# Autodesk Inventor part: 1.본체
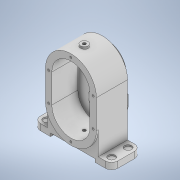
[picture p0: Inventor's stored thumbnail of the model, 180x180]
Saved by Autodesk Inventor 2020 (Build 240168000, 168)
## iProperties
Created: 2021-05
Part Number: 1.본체
Material: 일반
Document SubType Name: Modeling
Designer: Owner
Density: 1 g/cm^3
Appearance: 기본값
Author: Owner
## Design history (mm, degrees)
sketch "스케치1"
  geometry: L1 (0, 62.5)-(0, -62.5); L2 (40, 22.5)-(40, -22.5); L3 (-40, -22.5)-(-40, 22.5); A1 r 40 centre (0, 22.5) between (40, 22.5) and (-40, 22.5); A2 r 40 centre (0, -22.5) between (-40, -22.5) and (40, -22.5); 2 further points
  constraints: 8 end point, 6 point on circle, 4 tangent, 2 centre point, 2 point on line, 1 coincident, 1 midpoint, 1 parallel, 1 vertical
  dimensions: "d4" = 80 distance between parallel lines of L2 L3; "d5" = 45 distance of A2.centre A1.centre
extrude "돌출1" new body sketch "스케치1" distance "d6" = 49; taper "d7" = 0 deg
sketch "스케치2"
  geometry: L1 (0, 52.5)-(0, -52.5); L2 (-30, 22.5)-(-30, -22.5); L3 (30, -22.5)-(30, 22.5); A1 r 30 centre (0, 22.5) between (30, 22.5) and (-30, 22.5); A2 r 30 centre (0, -22.5) between (-30, -22.5) and (30, -22.5); 2 further points
  constraints: 8 end point, 6 point on circle, 4 tangent, 2 centre point, 2 point on line, 1 coincident, 1 midpoint, 1 parallel, 1 vertical
  dimensions: "d9" = 30 radius of A1; "d10" = 45 distance of A2.centre A1.centre
extrude "돌출2" cut sketch "스케치2" distance "d11" = 41; taper "d12" = 0 deg
sketch "스케치3"
  geometry: A1 r 40 centre (0, -22.5) between (-40, -22.5) and (40, -22.5) reference; A2 r 40 centre (0, 22.5) between (40, 22.5) and (-40, 22.5) reference; 1 further point
sketch "스케치4"
  geometry: L1 (-40, -22.5)-(-40, -59.5); L2 (-40, -59.5)-(-61, -59.5); L3 (-61, -59.5)-(-61, -69.5); L4 (-61, -69.5)-(-35, -69.5); L5 (-35, -69.5)-(-35, -64.5); L6 (-35, -64.5)-(0, -64.5); L7 (0, -64.5)-(0, -62.5); A1 r 40 centre (0, -22.5) between (-40, -22.5) and (40, -22.5) reference; 1 further point
  constraints: 14 end point, 6 perpendicular, 1 point on circle, 1 point on line, 1 tangent, 1 vertical
  dimensions: "d20" = 35 distance between parallel lines of L7 L5; "d21" = 10 distance of L2.end L3.end; "d22" = 5 distance between parallel lines of L6 L4; "d23" = 61 distance between parallel lines of L7 L3; "d24" = 47 distance from line of A1.centre L4
extrude "돌출3" join sketch "스케치4" distance "d25" = 46; taper "d26" = 0 deg
sketch "스케치5"
  geometry: L1 (0, 57.5)-(0, -57.5); L2 (-35, 22.5)-(-35, -22.5); L3 (35, -22.5)-(35, 22.5); A1 r 35 centre (0, 22.5) between (35, 22.5) and (-35, 22.5); A2 r 35 centre (0, -22.5) between (-35, -22.5) and (35, -22.5); 6 further points
  constraints: 8 end point, 6 point on circle, 5 coincident, 4 tangent, 2 centre point, 2 point on line, 1 midpoint, 1 parallel, 1 vertical
  dimensions: "d28" = 45 distance of A2.centre A1.centre
hole "구멍1" sketch "스케치5" diameter "d29" = 3.242; stored, may be unused: countersink angle "d33" = 82 deg, drill point angle "d35" = 118 deg; dims "d30" = 8, "d31" = 3.023, "d32" = 2, "d34" = 10
hole "구멍2" sketch "스케치5" diameter "d36" = 3.242; stored, may be unused: countersink angle "d40" = 82 deg, drill point angle "d42" = 118 deg; dims "d37" = 8, "d38" = 3.023, "d39" = 2, "d41" = 10
sketch "스케치6"
  geometry: 1 further point
node "작업 평면1"
sketch "스케치7"
  geometry: L1 (5, 49)-(-75, 49) reference; C1 r 6 at (-35, 28); 1 further point
  constraints: 1 centre point
  dimensions: "d44" = 21 distance from line of L1 C1.centre; "d45" = 12 diameter of C1
extrude "돌출4" join sketch "스케치7" stored distance "d46" = 46; taper "d47" = 0 deg
sketch "스케치8"
  geometry: L1 (-64.5, 0)-(-64.5, 46) reference; L2 (-52.5, 49)-(-22.5, 49) reference; 2 further points
  constraints: 1 point on line
  dimensions: "d48" = 21 distance from line of point (-64.5, 28) L2
sketch "스케치9"
  geometry: C1 r 6 at (-35, 28) reference; 2 further points
  constraints: 1 coincident
hole "구멍3" sketch "스케치9" at (-35, 28) diameter "d49" = 4.917; stored, may be unused: countersink angle "d53" = 82 deg, drill point angle "d55" = 118 deg; dims "d50" = 135, "d51" = 12, "d52" = 1, "d54" = 151.35
sketch "스케치10"
  geometry: L1 (0, 52.5)-(0, -52.5); L2 (-30, 22.5)-(-30, -22.5); L3 (30, -22.5)-(30, 22.5); A1 r 30 centre (0, 22.5) between (30, 22.5) and (-30, 22.5); A2 r 30 centre (0, -22.5) between (-30, -22.5) and (30, -22.5); 2 further points
  constraints: 8 end point, 6 point on circle, 4 tangent, 2 centre point, 2 point on line, 1 coincident, 1 midpoint, 1 parallel, 1 vertical
  dimensions: "d56" = 30 radius of A1; "d57" = 45 distance of A2.centre A1.centre
extrude "돌출5" join sketch "스케치10" distance "d58" = 11; taper "d59" = 0 deg
sketch "스케치11"
  geometry: 1 further point
sketch "스케치12"
  geometry: L1 (21, 0)-(21, -46) reference; L2 (21, -46)-(0, -46) reference; C1 r 5.5 at (11, -36); 1 further point
  constraints: 1 centre point
  dimensions: "d60" = 11 diameter of C1; "d61" = 10 distance from line of L1 C1.centre; "d62" = 10 distance from line of L2 C1.centre
fillet "모깎기1" dims "d63" = 10
sketch "스케치13"
  geometry: L1 (21, 0)-(21, -36) reference; L2 (0, 0)-(21, 0) reference; C1 r 5.5 at (11, -10); 1 further point
  constraints: 1 centre point
  dimensions: "d64" = 11 diameter of C1; "d65" = 10 distance from line of L1 C1.centre; "d66" = 10 distance from line of C1.centre L2
extrude "돌출6" cut sketch "스케치13" distance "d67" = 2; taper "d68" = 0 deg
extrude "돌출7" cut sketch "스케치12" distance "d69" = 2; taper "d70" = 0 deg
fillet "모깎기2" dims "d71" = 10
sketch "스케치14"
  geometry: L1 (-51, -69.5)-(-35, -69.5) reference; C1 r 14 at (0, 22.5); 1 further point
  constraints: 1 centre point, 1 vertical alignment
  dimensions: "d72" = 92 distance from line of L1 C1.centre; "d73" = 28 diameter of C1
extrude "돌출8" cut sketch "스케치14" distance "d74" = 7; taper "d75" = 0 deg
sketch "스케치15"
  geometry: L1 (51, -92)-(35, -92) reference; L2 (-40, 0)-(-40, -82) reference; L3 (-35, -92)-(-35, -87) reference; C1 r 11 at (0, 0); 1 further point
  constraints: 1 centre point
  dimensions: "d76" = 22 diameter of C1; "d77" = 92 distance from line of C1.centre L1; "d79" = 35 distance from line of L3 C1.centre
extrude "돌출9" cut sketch "스케치15" stored distance "d80" = 4; taper "d81" = 0 deg
sketch "스케치16"
  geometry: 1 further point
sketch "스케치17"
  geometry: C1 r 11 at (0, 22.5) reference; C2 r 14 at (0, 22.5); 1 further point
  constraints: 1 centre point, 1 coincident
  dimensions: "d82" = 28 diameter of C2
extrude "돌출10" cut sketch "스케치17" distance "d83" = 8; taper "d84" = 0 deg
sketch "스케치18"
  geometry: C1 r 14 at (0, -22.5); 1 further point
  constraints: 1 centre point
  dimensions: "d85" = 28 diameter of C1; "d86" = 22.5 distance of point (0, 0) C1.centre
extrude "돌출11" cut sketch "스케치18" distance "d87" = 8; taper "d88" = 0 deg
sketch "스케치19"
  geometry: C1 r 10 at (0, 0); 1 further point
  constraints: 1 centre point
  dimensions: "d89" = 20 diameter of C1
extrude "돌출12" cut sketch "스케치19" distance "d90" = 4; taper "d91" = 0 deg
sketch "스케치20"
  geometry: 1 further point
sketch "스케치21"
  geometry: 1 further point
sketch "스케치22"
  geometry: L1 (30, -22.5)-(30, 22.5) reference; L2 (-30, 22.5)-(-30, -22.5) reference; L3 (-30, 22.5)-(-30, -22.5) reference; L4 (-30, -7.5)-(30, -7.5); C1 r 14 at (0, 22.5) reference; A1 r 30 centre (0, 22.5) between (30, 22.5) and (-30, 22.5) reference; 2 further points
  constraints: 2 end point, 2 point on line, 1 perpendicular
  dimensions: "d92" = 30 distance from line of A1.centre L4
extrude "돌출13" cut sketch "스케치22" distance "d93" = 3; taper "d94" = 0 deg
node "솔리드1"
mirror "미러1"
mirror "미러2"
mirror "미러3"
mirror "미러4"
mirror "미러5"
feature "A9D066F2-1C7D-4E18-AEED-F7BC21143FA4" dims "d49" = 4.917, "d50" = 135, "d51" = 12, "d52" = 1, "d53" = 82 deg, "d54" = 151.35, "d55" = 118 deg
